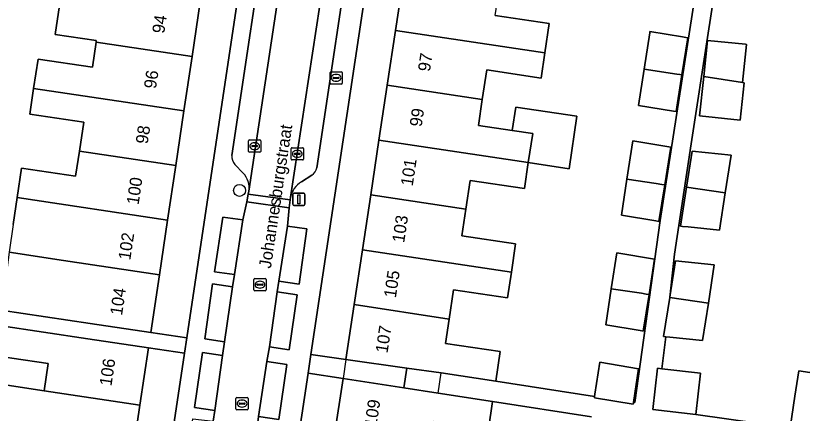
# Model space of a CAD drawing. Extents: x 163008 to 163854, y 382777 to 383982.
# Drawn here: x 163603.3 to 163667.4, y 383304.2 to 383336.6 of the extents above; entities that cross this region are included whole.
import ezdxf

# ---------------------------------------------------------------- set-up
doc = ezdxf.new("R2010")
doc.units = 0
for name, color, linetype in [('IMGEO_Boom', 7, 'Continuous'), ('IMGEO_Brandkraan', 7, 'Continuous'), ('IMGEO_Erf', 7, 'Continuous'), ('IMGEO_Kolk', 7, 'Continuous'), ('IMGEO_Lichtmast', 7, 'Continuous'), ('IMGEO_Openbare_ruimte_label', 7, 'Continuous'), ('IMGEO_Pand', 7, 'Continuous'), ('IMGEO_Pand_nummerreeks', 7, 'Continuous'), ('IMGEO_Pand_overbouw', 7, 'Continuous'), ('IMGEO_Parkeervlak_open', 7, 'Continuous'), ('IMGEO_Rijbaan_lokaal_open', 7, 'Continuous'), ('IMGEO_Voetpad_open', 7, 'Continuous')]:
    doc.layers.add(name, color=color, linetype=linetype)

msp = doc.modelspace()

# ---------------------------------------------------------------- linework, layer by layer
at = {"layer": 'IMGEO_Boom'}
msp.add_circle((163621.551, 383322.41), 0.489, dxfattribs=at)
at = {"layer": 'IMGEO_Brandkraan'}
for p, q in [((163628.921, 383331.156), (163628.921, 383332.008)), ((163628.996, 383332.082), (163629.848, 383332.082)), ((163629.18, 383331.576), (163629.18, 383331.588)), ((163629.618, 383331.539), (163629.22, 383331.539)), ((163629.223, 383331.625), (163629.621, 383331.625)), ((163629.409, 383331.862), (163629.434, 383331.862)), ((163629.664, 383331.588), (163629.664, 383331.576)), ((163629.922, 383332.008), (163629.922, 383331.156)), ((163629.848, 383331.082), (163628.996, 383331.082)), ((163629.432, 383331.302), (163629.407, 383331.302))]:
    msp.add_line(p, q, dxfattribs=at)
for points in [[(163628.921, 383331.156), (163628.921, 383332.008)], [(163628.996, 383332.082), (163629.848, 383332.082)], [(163629.922, 383332.008), (163629.922, 383331.156)], [(163629.848, 383331.082), (163628.996, 383331.082)]]:
    msp.add_lwpolyline(points, dxfattribs=at)
for centre, radius, start, end in [((163628.998, 383332.006), 0.0765, 91.55205, 178.44795), ((163628.998, 383332.006), 0.0765, 91.55205, 178.44795), ((163629.22, 383331.585), 0.0403, 85.87752, 175.75265), ((163629.217, 383331.575), 0.0366, 178.93798, 274.71019), ((163629.621, 383331.582), 0.043, 264.86636, 352.45326), ((163629.625, 383331.587), 0.0386, 1.73085, 96.63898), ((163629.846, 383332.006), 0.0765, 1.55205, 88.44795), ((163629.846, 383332.006), 0.0765, 1.55205, 88.44795), ((163628.998, 383331.158), 0.0765, 181.55205, 268.44795), ((163628.998, 383331.158), 0.0765, 181.55205, 268.44795), ((163629.846, 383331.158), 0.0765, 271.55205, 358.44795), ((163629.846, 383331.158), 0.0765, 271.55205, 358.44795)]:
    msp.add_arc(centre, radius, start, end, dxfattribs=at)
for centre, major_axis, ratio, start_param, end_param in [((163629.408, 383331.582), (-0.387, 0.002), 0.722429, 4.712389, 7.853982), ((163629.433, 383331.582), (-0.39, 0.002), 0.717154, 1.570796, 4.712389)]:
    msp.add_ellipse(centre, major_axis=major_axis, ratio=ratio, start_param=start_param, end_param=end_param, dxfattribs=at)
at = {"layer": 'IMGEO_Erf'}
for points in [[(163626.017, 383368.942), (163623.079, 383369.386), (163622.346, 383364.487), (163621.681, 383360.036), (163621.015, 383355.585), (163620.35, 383351.135), (163619.684, 383346.684), (163619.019, 383342.234), (163618.353, 383337.783), (163617.688, 383333.333), (163617.022, 383328.882), (163616.357, 383324.432), (163615.691, 383319.982), (163615.026, 383315.533), (163614.322, 383310.826), (163617.252, 383310.387)], [(163632.912, 383326.513), (163633.585, 383330.983), (163634.258, 383335.452), (163634.931, 383339.922), (163635.604, 383344.391), (163636.277, 383348.861), (163636.95, 383353.33), (163637.623, 383357.8), (163638.296, 383362.27), (163639.024, 383367.102), (163636.157, 383367.519), (163627.364, 383309.04), (163630.216, 383308.611), (163630.891, 383313.093), (163631.566, 383317.573), (163632.239, 383322.043)], [(163657.596, 383331.826), (163657.131, 383328.83), (163656.92, 383328.864), (163654.048, 383329.334), (163654.507, 383332.292), (163654.967, 383335.257), (163654.981, 383335.351), (163657.651, 383334.914), (163657.902, 383334.873), (163658.064, 383334.846)], [(163662.663, 383331.191), (163662.341, 383328.13), (163659.034, 383328.478), (163659.371, 383331.685), (163659.682, 383334.642), (163662.765, 383334.318), (163662.862, 383334.308), (163662.536, 383331.21)], [(163653.116, 383323.33), (163653.599, 383326.441), (163656.682, 383325.937), (163656.205, 383322.864), (163655.718, 383319.886), (163655.48, 383319.925), (163652.659, 383320.386)], [(163661.119, 383322.213), (163660.645, 383319.161), (163658.104, 383319.428), (163657.642, 383319.477), (163657.484, 383319.494), (163657.979, 383322.684), (163658.435, 383325.619), (163661.596, 383325.286)], [(163654.924, 383313.924), (163654.437, 383310.944), (163654.188, 383310.985), (163651.38, 383311.444), (163651.837, 383314.389), (163652.29, 383317.31), (163655.371, 383316.806)], [(163617.064, 383309.129), (163614.133, 383309.568), (163613.435, 383304.901), (163612.765, 383300.418), (163612.095, 383295.936), (163611.424, 383291.454), (163610.754, 383286.972), (163610.084, 383282.49), (163609.414, 383278.008), (163608.744, 383273.526), (163608.073, 383269.044), (163607.403, 383264.561), (163606.733, 383260.079), (163606.062, 383255.594), (163605.388, 383251.086), (163608.303, 383250.604)], [(163625.915, 383280.05), (163626.586, 383284.503), (163627.256, 383288.957), (163627.927, 383293.411), (163628.598, 383297.865), (163629.269, 383302.324), (163629.986, 383307.085), (163627.135, 383307.514), (163618.487, 383250), (163618.346, 383249.06), (163620.803, 383248.742), (163620.284, 383245.414), (163620.668, 383245.357), (163621.015, 383247.666), (163621.194, 383248.7), (163621.39, 383250), (163621.892, 383253.327), (163622.562, 383257.78), (163623.232, 383262.235), (163623.903, 383266.688), (163624.574, 383271.142), (163625.244, 383275.595)]]:
    msp.add_lwpolyline(points, close=True, dxfattribs=at)
for points in [[(163679.889, 383360.907), (163664.081, 383363.249), (163659.743, 383335.218), (163658.351, 383326.217), (163656.981, 383317.216), (163656.609, 383313.683), (163656.621, 383313.742), (163657.071, 383316.66), (163660.231, 383316.328), (163659.748, 383313.212), (163659.274, 383310.16), (163656.61, 383310.44), (163656.272, 383310.476), (163655.965, 383307.874), (163659.102, 383307.514), (163658.715, 383304.141), (163666.408, 383303.048), (163666.795, 383305.63), (163667.104, 383307.692), (163671.602, 383307.017)], [(163642.379, 383336.674), (163646.79, 383336.01), (163646.43, 383333.617), (163646.121, 383331.568), (163641.688, 383332.236), (163641.323, 383329.816), (163641.006, 383327.708), (163643.763, 383327.293), (163644.051, 383329.207), (163649.038, 383328.456), (163648.394, 383324.178), (163645.079, 383324.678), (163644.758, 383322.551), (163640.346, 383323.215), (163639.994, 383320.875), (163639.668, 383318.711), (163644.046, 383318.052), (163643.698, 383315.744), (163643.382, 383313.643), (163638.984, 383314.306), (163638.625, 383311.924), (163638.325, 383309.933), (163642.781, 383309.262), (163642.419, 383306.861), (163650.476, 383305.615), (163650.505, 383305.805), (163650.907, 383308.397), (163654.063, 383307.859), (163653.638, 383305.126), (163653.757, 383305.108), (163655.823, 383319.949), (163660.643, 383351.122)], [(163603.099, 383319.625), (163603.427, 383321.819), (163603.787, 383324.226), (163608.196, 383323.566), (163608.502, 383325.609), (163608.857, 383327.978), (163604.464, 383328.636), (163604.775, 383330.717), (163605.134, 383333.116), (163609.558, 383332.455), (163609.865, 383334.506), (163609.883, 383334.629), (163606.53, 383335.131), (163606.881, 383337.483)], [(163600.516, 383302.251), (163600.863, 383304.571), (163601.187, 383306.734), (163605.638, 383306.068), (163605.97, 383308.288), (163602.995, 383308.733), (163601.563, 383308.947), (163601.929, 383311.395), (163594.409, 383312.154), (163594.108, 383309.145), (163591.043, 383309.451), (163590.774, 383306.762), (163593.512, 383306.37), (163593.092, 383303.437)], [(163650.217, 383303.952), (163642.171, 383305.204), (163641.83, 383302.939)]]:
    msp.add_lwpolyline(points, dxfattribs=at)
at = {"layer": 'IMGEO_Kolk'}
for p, q in [((163622.282, 383325.592), (163622.282, 383326.444)), ((163622.357, 383326.518), (163623.209, 383326.518)), ((163623.283, 383326.444), (163623.283, 383325.592)), ((163622.541, 383326.012), (163622.541, 383326.024)), ((163622.979, 383325.975), (163622.581, 383325.975)), ((163622.584, 383326.061), (163622.982, 383326.061)), ((163622.793, 383325.738), (163622.768, 383325.738)), ((163622.77, 383326.298), (163622.795, 383326.298)), ((163623.025, 383326.024), (163623.025, 383326.012)), ((163625.753, 383324.961), (163625.753, 383325.813)), ((163625.828, 383325.887), (163626.68, 383325.887)), ((163626.754, 383325.813), (163626.754, 383324.961)), ((163623.209, 383325.518), (163622.357, 383325.518)), ((163626.012, 383325.381), (163626.012, 383325.393)), ((163626.45, 383325.344), (163626.052, 383325.344)), ((163626.055, 383325.43), (163626.453, 383325.43)), ((163626.264, 383325.107), (163626.239, 383325.107)), ((163626.241, 383325.667), (163626.266, 383325.667)), ((163626.496, 383325.393), (163626.496, 383325.381)), ((163626.68, 383324.887), (163625.828, 383324.887)), ((163622.713, 383314.296), (163622.713, 383315.148)), ((163622.788, 383315.222), (163623.64, 383315.222)), ((163623.201, 383315.002), (163623.226, 383315.002)), ((163623.714, 383315.148), (163623.714, 383314.296)), ((163623.64, 383314.222), (163622.788, 383314.222)), ((163622.972, 383314.716), (163622.972, 383314.728)), ((163623.41, 383314.679), (163623.012, 383314.679)), ((163623.015, 383314.765), (163623.413, 383314.765)), ((163623.224, 383314.442), (163623.199, 383314.442)), ((163623.456, 383314.728), (163623.456, 383314.716)), ((163621.257, 383304.602), (163621.257, 383305.454)), ((163621.332, 383305.528), (163622.184, 383305.528)), ((163621.745, 383305.308), (163621.77, 383305.308)), ((163622.258, 383305.454), (163622.258, 383304.602)), ((163621.516, 383305.022), (163621.516, 383305.034)), ((163621.954, 383304.985), (163621.556, 383304.985)), ((163621.559, 383305.071), (163621.957, 383305.071)), ((163621.768, 383304.748), (163621.743, 383304.748)), ((163622, 383305.034), (163622, 383305.022)), ((163622.184, 383304.528), (163621.332, 383304.528))]:
    msp.add_line(p, q, dxfattribs=at)
for points in [[(163622.282, 383325.592), (163622.282, 383326.444)], [(163622.357, 383326.518), (163623.209, 383326.518)], [(163623.283, 383326.444), (163623.283, 383325.592)], [(163625.753, 383324.961), (163625.753, 383325.813)], [(163625.828, 383325.887), (163626.68, 383325.887)], [(163626.754, 383325.813), (163626.754, 383324.961)], [(163623.209, 383325.518), (163622.357, 383325.518)], [(163626.68, 383324.887), (163625.828, 383324.887)], [(163622.713, 383314.296), (163622.713, 383315.148)], [(163622.788, 383315.222), (163623.64, 383315.222)], [(163623.714, 383315.148), (163623.714, 383314.296)], [(163623.64, 383314.222), (163622.788, 383314.222)], [(163621.257, 383304.602), (163621.257, 383305.454)], [(163621.332, 383305.528), (163622.184, 383305.528)], [(163622.258, 383305.454), (163622.258, 383304.602)], [(163622.184, 383304.528), (163621.332, 383304.528)]]:
    msp.add_lwpolyline(points, dxfattribs=at)
for centre, radius, start, end in [((163622.359, 383326.442), 0.0765, 91.55205, 178.44795), ((163622.359, 383326.442), 0.0765, 91.55205, 178.44795), ((163623.207, 383326.442), 0.0765, 1.55205, 88.44795), ((163623.207, 383326.442), 0.0765, 1.55205, 88.44795), ((163622.581, 383326.021), 0.0403, 85.87752, 175.75265), ((163622.578, 383326.011), 0.0366, 178.93798, 274.71019), ((163622.982, 383326.018), 0.043, 264.86636, 352.45326), ((163622.986, 383326.023), 0.0386, 1.73085, 96.63898), ((163625.83, 383325.811), 0.0765, 91.55205, 178.44795), ((163625.83, 383325.811), 0.0765, 91.55205, 178.44795), ((163626.678, 383325.811), 0.0765, 1.55205, 88.44795), ((163626.678, 383325.811), 0.0765, 1.55205, 88.44795), ((163622.359, 383325.594), 0.0765, 181.55205, 268.44795), ((163622.359, 383325.594), 0.0765, 181.55205, 268.44795), ((163623.207, 383325.594), 0.0765, 271.55205, 358.44795), ((163623.207, 383325.594), 0.0765, 271.55205, 358.44795), ((163626.052, 383325.39), 0.0403, 85.87752, 175.75265), ((163626.049, 383325.38), 0.0366, 178.93798, 274.71019), ((163626.453, 383325.387), 0.043, 264.86636, 352.45326), ((163626.457, 383325.392), 0.0386, 1.73085, 96.63898), ((163625.83, 383324.963), 0.0765, 181.55205, 268.44795), ((163625.83, 383324.963), 0.0765, 181.55205, 268.44795), ((163626.678, 383324.963), 0.0765, 271.55205, 358.44795), ((163626.678, 383324.963), 0.0765, 271.55205, 358.44795), ((163622.79, 383315.146), 0.0765, 91.55205, 178.44795), ((163622.79, 383315.146), 0.0765, 91.55205, 178.44795), ((163623.638, 383315.146), 0.0765, 1.55205, 88.44795), ((163623.638, 383315.146), 0.0765, 1.55205, 88.44795), ((163622.79, 383314.298), 0.0765, 181.55205, 268.44795), ((163622.79, 383314.298), 0.0765, 181.55205, 268.44795), ((163623.012, 383314.725), 0.0403, 85.87752, 175.75265), ((163623.009, 383314.715), 0.0366, 178.93798, 274.71019), ((163623.413, 383314.722), 0.043, 264.86636, 352.45326), ((163623.417, 383314.727), 0.0386, 1.73085, 96.63898), ((163623.638, 383314.298), 0.0765, 271.55205, 358.44795), ((163623.638, 383314.298), 0.0765, 271.55205, 358.44795), ((163621.334, 383305.452), 0.0765, 91.55205, 178.44795), ((163621.334, 383305.452), 0.0765, 91.55205, 178.44795), ((163622.182, 383305.452), 0.0765, 1.55205, 88.44795), ((163622.182, 383305.452), 0.0765, 1.55205, 88.44795), ((163621.334, 383304.604), 0.0765, 181.55205, 268.44795), ((163621.334, 383304.604), 0.0765, 181.55205, 268.44795), ((163621.556, 383305.031), 0.0403, 85.87752, 175.75265), ((163621.553, 383305.021), 0.0366, 178.93798, 274.71019), ((163621.957, 383305.028), 0.043, 264.86636, 352.45326), ((163621.961, 383305.033), 0.0386, 1.73085, 96.63898), ((163622.182, 383304.604), 0.0765, 271.55205, 358.44795), ((163622.182, 383304.604), 0.0765, 271.55205, 358.44795)]:
    msp.add_arc(centre, radius, start, end, dxfattribs=at)
for centre, major_axis, ratio, start_param, end_param in [((163622.769, 383326.018), (-0.387, 0.002), 0.722429, 4.712389, 7.853982), ((163622.794, 383326.018), (-0.39, 0.002), 0.717154, 1.570796, 4.712389), ((163626.24, 383325.387), (-0.387, 0.002), 0.722429, 4.712389, 7.853982), ((163626.265, 383325.387), (-0.39, 0.002), 0.717154, 1.570796, 4.712389), ((163623.2, 383314.722), (-0.387, 0.002), 0.722429, 4.712389, 7.853982), ((163623.225, 383314.722), (-0.39, 0.002), 0.717154, 1.570796, 4.712389), ((163621.744, 383305.028), (-0.387, 0.002), 0.722429, 4.712389, 7.853982), ((163621.769, 383305.028), (-0.39, 0.002), 0.717154, 1.570796, 4.712389)]:
    msp.add_ellipse(centre, major_axis=major_axis, ratio=ratio, start_param=start_param, end_param=end_param, dxfattribs=at)
at = {"layer": 'IMGEO_Lichtmast'}
for p, q in [((163625.888, 383321.278), (163625.888, 383322.078)), ((163625.888, 383322.078), (163625.888, 383321.278)), ((163625.988, 383322.178), (163626.778, 383322.178)), ((163626.778, 383322.178), (163625.988, 383322.178)), ((163626.878, 383322.078), (163626.878, 383321.278)), ((163626.878, 383321.278), (163626.878, 383322.078)), ((163626.778, 383321.178), (163625.988, 383321.178)), ((163625.988, 383321.178), (163626.778, 383321.178))]:
    msp.add_line(p, q, dxfattribs=at)
msp.add_lwpolyline([(163626.308, 383322.053), (163626.458, 383322.053), (163626.458, 383321.303), (163626.308, 383321.303), (163626.308, 383322.053)], dxfattribs=at)
for centre, start, end in [((163625.988, 383322.078), 90, 180), ((163625.988, 383322.078), 90, 180), ((163626.778, 383322.078), 0, 90), ((163626.778, 383322.078), 360, 90), ((163625.988, 383321.278), 180, 270), ((163625.988, 383321.278), 180, 270), ((163626.778, 383321.278), 270, 0), ((163626.778, 383321.278), 270, 0)]:
    msp.add_arc(centre, 0.1, start, end, dxfattribs=at)
at = {"layer": 'IMGEO_Pand'}
for points in [[(163634.931, 383339.922), (163634.258, 383335.452), (163646.43, 383333.617), (163646.79, 383336.01), (163642.379, 383336.674), (163642.692, 383338.752)], [(163618.353, 383337.783), (163606.037, 383339.629), (163605.742, 383337.653), (163606.881, 383337.483), (163606.53, 383335.131), (163609.883, 383334.629), (163609.865, 383334.506), (163617.688, 383333.333)], [(163646.43, 383333.617), (163634.258, 383335.452), (163633.585, 383330.983), (163641.323, 383329.816), (163641.688, 383332.236), (163646.121, 383331.568)], [(163654.507, 383332.292), (163657.187, 383331.887), (163657.409, 383331.854), (163657.596, 383331.826), (163658.064, 383334.846), (163657.902, 383334.873), (163657.651, 383334.914), (163654.981, 383335.351), (163654.967, 383335.257)], [(163617.688, 383333.333), (163609.865, 383334.506), (163609.558, 383332.455), (163605.134, 383333.116), (163604.775, 383330.717), (163617.022, 383328.882)], [(163659.371, 383331.685), (163662.536, 383331.21), (163662.862, 383334.308), (163662.765, 383334.318), (163659.682, 383334.642)], [(163657.596, 383331.826), (163657.409, 383331.854), (163657.187, 383331.887), (163654.507, 383332.292), (163654.048, 383329.334), (163656.92, 383328.864), (163657.131, 383328.83)], [(163662.663, 383331.191), (163662.536, 383331.21), (163659.371, 383331.685), (163659.034, 383328.478), (163662.341, 383328.13)], [(163641.323, 383329.816), (163633.585, 383330.983), (163632.912, 383326.513), (163645.079, 383324.678), (163645.435, 383327.041), (163643.763, 383327.293), (163641.006, 383327.708)], [(163617.022, 383328.882), (163604.775, 383330.717), (163604.464, 383328.636), (163608.857, 383327.978), (163608.502, 383325.609), (163616.357, 383324.432)], [(163643.763, 383327.293), (163645.435, 383327.041), (163645.079, 383324.678), (163648.394, 383324.178), (163649.038, 383328.456), (163644.051, 383329.207)], [(163632.912, 383326.513), (163632.239, 383322.043), (163639.994, 383320.875), (163640.346, 383323.215), (163644.758, 383322.551), (163645.079, 383324.678)], [(163653.116, 383323.33), (163655.502, 383322.97), (163655.966, 383322.9), (163656.205, 383322.864), (163656.682, 383325.937), (163653.599, 383326.441)], [(163615.691, 383319.982), (163616.357, 383324.432), (163608.502, 383325.609), (163608.196, 383323.566), (163603.787, 383324.226), (163603.427, 383321.819)], [(163657.979, 383322.684), (163661.119, 383322.213), (163661.596, 383325.286), (163658.435, 383325.619)], [(163656.205, 383322.864), (163655.966, 383322.9), (163655.502, 383322.97), (163653.116, 383323.33), (163652.659, 383320.386), (163655.48, 383319.925), (163655.718, 383319.886)], [(163661.119, 383322.213), (163657.979, 383322.684), (163657.484, 383319.494), (163657.642, 383319.477), (163658.104, 383319.428), (163660.645, 383319.161)], [(163643.698, 383315.744), (163644.046, 383318.052), (163639.668, 383318.711), (163639.994, 383320.875), (163632.239, 383322.043), (163631.566, 383317.573)], [(163615.691, 383319.982), (163603.427, 383321.819), (163603.099, 383319.625), (163602.792, 383317.366), (163607.218, 383316.703), (163615.026, 383315.533)], [(163638.625, 383311.924), (163638.984, 383314.306), (163643.382, 383313.643), (163643.698, 383315.744), (163631.566, 383317.573), (163630.891, 383313.093)], [(163615.026, 383315.533), (163607.218, 383316.703), (163602.792, 383317.366), (163602.508, 383315.275), (163602.45, 383314.891), (163602.115, 383312.652), (163609.378, 383311.566), (163614.322, 383310.826)], [(163651.837, 383314.389), (163654.294, 383314.019), (163654.674, 383313.962), (163654.924, 383313.924), (163655.371, 383316.806), (163652.29, 383317.31)], [(163656.609, 383313.683), (163659.748, 383313.212), (163660.231, 383316.328), (163657.071, 383316.66), (163656.621, 383313.742)], [(163654.924, 383313.924), (163654.674, 383313.962), (163654.294, 383314.019), (163651.837, 383314.389), (163651.38, 383311.444), (163654.188, 383310.985), (163654.437, 383310.944)], [(163659.748, 383313.212), (163656.609, 383313.683), (163656.089, 383310.495), (163656.272, 383310.476), (163656.61, 383310.44), (163659.274, 383310.16)], [(163638.625, 383311.924), (163630.891, 383313.093), (163630.216, 383308.611), (163635.168, 383307.921), (163637.976, 383307.53), (163642.419, 383306.861), (163642.781, 383309.262), (163638.325, 383309.933)], [(163614.133, 383309.568), (163609.189, 383310.308), (163601.929, 383311.395), (163601.563, 383308.947), (163602.995, 383308.733), (163605.97, 383308.288), (163605.638, 383306.068), (163613.435, 383304.901)], [(163650.505, 383305.805), (163650.476, 383305.615), (163650.459, 383305.508), (163653.614, 383304.969), (163653.638, 383305.126), (163654.063, 383307.859), (163650.907, 383308.397)], [(163659.102, 383307.514), (163655.965, 383307.874), (163655.602, 383307.916), (163655.215, 383304.543), (163658.715, 383304.141)], [(163679.333, 383305.856), (163671.602, 383307.017), (163667.104, 383307.692), (163666.795, 383305.63), (163666.408, 383303.048), (163670.912, 383302.373), (163673.691, 383301.96), (163678.637, 383301.225)], [(163613.435, 383304.901), (163605.638, 383306.068), (163601.187, 383306.734), (163600.863, 383304.571), (163600.516, 383302.251), (163612.765, 383300.418)], [(163629.269, 383302.324), (163637.015, 383301.155), (163637.385, 383303.608), (163641.83, 383302.939), (163642.171, 383305.204), (163637.727, 383305.873), (163634.926, 383306.312), (163629.986, 383307.085)]]:
    msp.add_lwpolyline(points, close=True, dxfattribs=at)
at = {"layer": 'IMGEO_Pand_overbouw'}
for points in [[(163634.926, 383306.312), (163635.168, 383307.921), (163630.216, 383308.611), (163629.986, 383307.085)], [(163637.976, 383307.53), (163635.168, 383307.921), (163634.926, 383306.312), (163637.727, 383305.873)]]:
    msp.add_lwpolyline(points, close=True, dxfattribs=at)
at = {"layer": 'IMGEO_Parkeervlak_open'}
for points in [[(163622.309, 383322.342), (163629.103, 383367.415)], [(163632.469, 383366.928), (163631.712, 383362.058), (163628.995, 383343.4), (163625.711, 383321.848)], [(163624.046, 383346.1), (163620.934, 383325.265)], [(163627.859, 383324.261), (163630.98, 383345.098)], [(163621.165, 383324.528), (163621.851, 383323.82)], [(163626.592, 383323.106), (163627.433, 383323.642)]]:
    msp.add_lwpolyline(points, dxfattribs=at)
for points in [[(163621.806, 383320.011), (163620.186, 383320.23), (163619.498, 383315.767), (163621.152, 383315.54)], [(163624.75, 383315.017), (163626.406, 383314.773), (163627.046, 383319.27), (163625.462, 383319.502)], [(163619.348, 383314.786), (163618.712, 383310.303), (163620.326, 383310.068), (163620.987, 383314.543)], [(163624.616, 383314.127), (163623.98, 383309.644), (163625.594, 383309.409), (163626.255, 383313.884)], [(163619.533, 383304.478), (163620.158, 383308.956), (163618.543, 383309.192), (163617.885, 383304.72)], [(163624.755, 383303.737), (163625.406, 383308.216), (163623.763, 383308.45), (163623.109, 383303.985)]]:
    msp.add_lwpolyline(points, close=True, dxfattribs=at)
for centre, radius, start, end in [((163621.876, 383325.155), 0.948, 173.36013, 221.44528), ((163620.529, 383322.6), 1.799, 351.73888, 42.69526), ((163626.903, 383324.463), 0.977, 302.83659, 348.09139), ((163627.498, 383321.534), 1.815, 119.96143, 170.03008)]:
    msp.add_arc(centre, radius, start, end, dxfattribs=at)
at = {"layer": 'IMGEO_Rijbaan_lokaal_open'}
for points in [[(163625.683, 383321.628), (163625.711, 383321.848), (163628.995, 383343.4), (163631.712, 383362.058), (163632.469, 383366.928), (163632.535, 383367.35), (163629.166, 383367.856), (163629.103, 383367.415), (163622.309, 383322.342), (163622.266, 383322.099)], [(163625.683, 383321.628), (163622.266, 383322.099), (163622.153, 383321.469), (163625.602, 383320.993)], [(163623.763, 383308.45), (163623.98, 383309.644), (163624.616, 383314.127), (163624.75, 383315.017), (163625.462, 383319.502), (163625.602, 383320.993), (163622.153, 383321.469), (163621.806, 383320.011), (163621.152, 383315.54), (163620.987, 383314.543), (163620.326, 383310.068), (163620.158, 383308.956), (163619.533, 383304.478), (163619.395, 383303.584), (163618.727, 383299.103), (163618.697, 383297.877), (163622.019, 383297.425), (163622.34, 383298.594), (163622.984, 383303.076), (163623.109, 383303.985)]]:
    msp.add_lwpolyline(points, close=True, dxfattribs=at)
at = {"layer": 'IMGEO_Voetpad_open'}
for points in [[(163629.103, 383367.415), (163629.166, 383367.856), (163629.256, 383368.49), (163626.017, 383368.942), (163617.252, 383310.387), (163617.064, 383309.129), (163608.303, 383250.604), (163611.443, 383250.058), (163611.551, 383250.689), (163611.614, 383251.055)], [(163627.135, 383307.514), (163627.364, 383309.04), (163636.157, 383367.519), (163632.635, 383367.982), (163632.535, 383367.35), (163632.469, 383366.928)], [(163670.912, 383302.373), (163666.408, 383303.048), (163658.715, 383304.141), (163655.215, 383304.543), (163655.602, 383307.916), (163655.965, 383307.874), (163656.272, 383310.476), (163656.089, 383310.495), (163656.609, 383313.683), (163656.981, 383317.216), (163658.351, 383326.217), (163659.743, 383335.218), (163664.081, 383363.249), (163679.889, 383360.907)], [(163660.643, 383351.122), (163655.823, 383319.949), (163653.757, 383305.108), (163653.638, 383305.126), (163653.614, 383304.969), (163650.459, 383305.508), (163650.476, 383305.615), (163642.419, 383306.861), (163637.976, 383307.53), (163635.168, 383307.921), (163630.216, 383308.611), (163627.364, 383309.04), (163627.135, 383307.514), (163629.986, 383307.085), (163634.926, 383306.312), (163637.727, 383305.873), (163642.171, 383305.204), (163650.217, 383303.952)], [(163620.934, 383325.265), (163624.046, 383346.1)], [(163630.98, 383345.098), (163627.859, 383324.261)], [(163621.851, 383323.82), (163621.165, 383324.528)], [(163627.433, 383323.642), (163626.592, 383323.106)], [(163618.697, 383297.877), (163618.727, 383299.103), (163617.102, 383299.329), (163617.74, 383303.798), (163619.395, 383303.584), (163619.533, 383304.478), (163617.885, 383304.72), (163618.543, 383309.192), (163620.158, 383308.956), (163620.326, 383310.068), (163618.712, 383310.303), (163619.348, 383314.786), (163620.987, 383314.543), (163621.152, 383315.54), (163619.498, 383315.767), (163620.186, 383320.23), (163621.806, 383320.011), (163622.153, 383321.469), (163622.266, 383322.099), (163622.309, 383322.342)], [(163625.711, 383321.848), (163625.683, 383321.628), (163625.602, 383320.993), (163625.462, 383319.502), (163627.046, 383319.27), (163626.406, 383314.773), (163624.75, 383315.017), (163624.616, 383314.127), (163626.255, 383313.884), (163625.594, 383309.409), (163623.98, 383309.644), (163623.763, 383308.45), (163625.406, 383308.216), (163624.755, 383303.737), (163623.109, 383303.985), (163622.984, 383303.076), (163624.606, 383302.837), (163623.974, 383298.368), (163622.34, 383298.594), (163622.019, 383297.425), (163621.924, 383296.792), (163621.871, 383296.439)], [(163601.929, 383311.395), (163609.189, 383310.308), (163614.133, 383309.568), (163617.064, 383309.129), (163617.252, 383310.387), (163614.322, 383310.826), (163609.378, 383311.566), (163602.115, 383312.652)], [(163615.006, 383250.516), (163614.953, 383250.174), (163614.926, 383250), (163614.854, 383249.541), (163618.346, 383249.06), (163618.487, 383250), (163627.135, 383307.514)]]:
    msp.add_lwpolyline(points, dxfattribs=at)
for centre, radius, start, end in [((163621.876, 383325.155), 0.948, 173.36013, 221.44528), ((163620.529, 383322.6), 1.799, 351.73888, 42.69526), ((163626.903, 383324.463), 0.977, 302.83659, 348.09139), ((163627.498, 383321.534), 1.815, 119.96143, 170.03008)]:
    msp.add_arc(centre, radius, start, end, dxfattribs=at)

# ---------------------------------------------------------------- texts
at = {"layer": 'IMGEO_Openbare_ruimte_label'}
msp.add_text('Johannesburgstraat', height=1, rotation=81.48907, dxfattribs=at).set_placement((163624.1, 383316.003))
at = {"layer": 'IMGEO_Pand_nummerreeks'}
for s, rotation, p in [('94', 81.49752, (163615.413, 383335.156)), ('97', 81.43633, (163637.063, 383332.051)), ('96', 81.49507, (163614.739, 383330.652)), ('99', 81.43449, (163636.385, 383327.552)), ('98', 81.49752, (163614.066, 383326.15)), ('101', 81.43633, (163635.656, 383322.71)), ('100', 81.49507, (163613.324, 383321.191)), ('103', 81.43633, (163634.962, 383318.098)), ('102', 81.49507, (163612.649, 383316.681)), ('105', 81.43633, (163634.284, 383313.599)), ('104', 81.49752, (163611.976, 383312.177)), ('107', 81.43633, (163633.606, 383309.1)), ('106', 81.49752, (163611.114, 383306.418)), ('109', 81.43637, (163632.7, 383303.079))]:
    msp.add_text(s, height=1, rotation=rotation, dxfattribs=at).set_placement(p)

doc.saveas('drawing.dxf')
